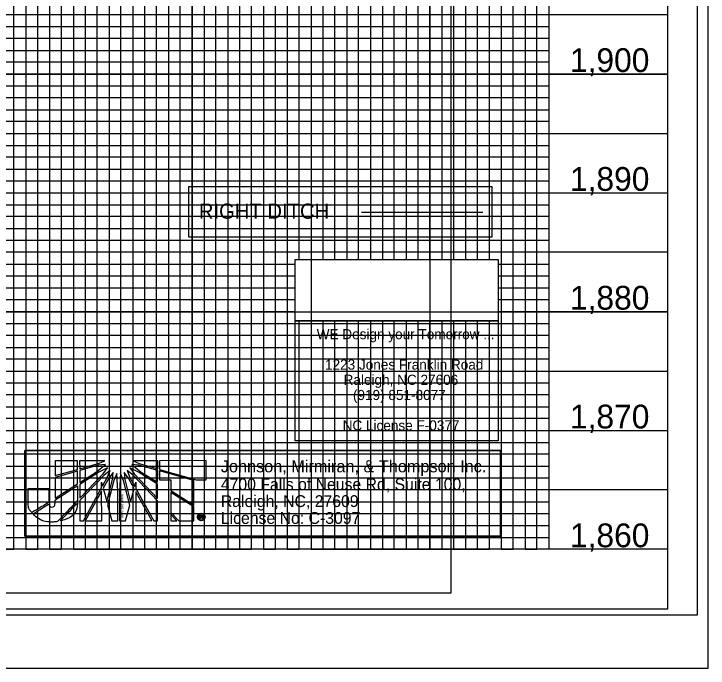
# Model space of a CAD drawing. Extents: x 557032 to 558930, y 525869 to 527437.
# Drawn here: x 558424.4 to 558716.5, y 525869.2 to 526144.6 of the extents above; entities that cross this region are included whole.
import ezdxf

# ---------------------------------------------------------------- set-up
doc = ezdxf.new("R2010")
doc.units = 0
for name, color, linetype in [('Exist Vertical Profile Vertical Axis Label', 7, 'Continuous'), ('Prop DSN Text', 7, 'Continuous'), ('Prop Grid Mask', 7, 'Continuous'), ('Prop PFL Ditch Label CELL', 7, 'Continuous'), ('Prop Vertical Profile Curve Label', 7, 'Continuous'), ('Prop VPI Label', 7, 'Continuous'), ('Raster_Level_4', 7, 'Continuous'), ('Sheet Cutting Line CELL', 7, 'Continuous'), ('Sheet DOT Grid CELL', 7, 'Continuous'), ('Sheet Layout Profile Border Port 2', 7, 'Continuous'), ('Sheet Plot Border Inside CELL', 7, 'Continuous'), ('Sheet Plot Border Outside CELL', 7, 'Continuous'), ('Sheet Profile CELL', 7, 'Continuous'), ('Sheet Profile Grid Major CELL', 7, 'Continuous'), ('Sheet Profile Grid Middle CELL', 7, 'Continuous'), ('Sheet Profile Grid Minor CELL', 7, 'Continuous')]:
    doc.layers.add(name, color=color, linetype=linetype)

msp = doc.modelspace()

# ---------------------------------------------------------------- linework, layer by layer
at = {"layer": 'Prop DSN Text'}
for p, q in [((558542.78, 525964.85), (558542.78, 526041.24)), ((558542.78, 526041.24), (558628.11, 526041.24)), ((558628.11, 526041.24), (558628.11, 525964.85)), ((558628.11, 526015.44), (558542.78, 526015.44)), ((558628.11, 525964.85), (558542.78, 525964.85))]:
    msp.add_line(p, q, dxfattribs=at)
at = {"layer": 'Prop Grid Mask'}
msp.add_lwpolyline([(558498, 526071.88), (558625.5, 526071.88), (558625.5, 526050.63), (558498, 526050.63)], close=True, dxfattribs=at)
at = {"layer": 'Prop PFL Ditch Label CELL'}
for p, q in [((558570.72, 526061.12), (558621.72, 526061.12)), ((558498, 526059.13), (558498, 526059.13))]:
    msp.add_line(p, q, dxfattribs=at)
at = {"layer": 'Prop Vertical Profile Curve Label'}
for p, q in [((558451.13, 525956.44), (558441.77, 525956.43)), ((558441.77, 525956.43), (558441.78, 525950.22)), ((558451.13, 525952.83), (558451.13, 525956.44)), ((558462.64, 525956.5), (558452.1, 525956.49)), ((558452.1, 525956.49), (558452.11, 525953.14)), ((558459.95, 525955.31), (558462.64, 525956.5)), ((558484.95, 525956.47), (558474.56, 525956.51)), ((558474.56, 525956.51), (558477.19, 525955.28)), ((558484.95, 525953.11), (558484.95, 525956.47)), ((558505.35, 525956.54), (558485.67, 525956.52)), ((558485.67, 525956.52), (558485.67, 525952.91)), ((558505.36, 525948.48), (558505.35, 525956.54)), ((558452.11, 525953.14), (558459.95, 525955.31)), ((558459.95, 525954.58), (558452.11, 525952.41)), ((558459.14, 525951.8), (558463.01, 525954.95)), ((558463.01, 525954.95), (558459.95, 525954.58)), ((558463.78, 525953.5), (558460.22, 525951.69)), ((558461.98, 525950.97), (558463.78, 525953.5)), ((558473.22, 525953.51), (558475.03, 525950.93)), ((558476.84, 525951.71), (558473.22, 525953.51)), ((558474.04, 525954.97), (558477.97, 525951.76)), ((558476.93, 525954.6), (558474.04, 525954.97)), ((558484.95, 525952.4), (558476.93, 525954.6)), ((558477.19, 525955.28), (558484.95, 525953.11)), ((558441.78, 525950.22), (558451.13, 525952.83)), ((558451.13, 525952.15), (558441.78, 525949.51)), ((558451.14, 525946.73), (558451.13, 525952.15)), ((558452.11, 525952.41), (558452.11, 525947.34)), ((558452.11, 525947.34), (558459.14, 525951.8)), ((558460.22, 525951.69), (558452.11, 525946.53)), ((558452.12, 525940.69), (558461.98, 525950.97)), ((558462.38, 525950.46), (558452.12, 525939.7)), ((558464.87, 525952.38), (558462.38, 525950.46)), ((558463.73, 525949.38), (558464.87, 525952.38)), ((558466.21, 525951.54), (558464.36, 525949.16)), ((558465.95, 525948.66), (558466.21, 525951.54)), ((558467.76, 525951.13), (558466.48, 525948.13)), ((558468.17, 525943.74), (558467.76, 525951.13)), ((558469.3, 525951.13), (558468.83, 525943.75)), ((558470.54, 525948.13), (558469.3, 525951.13)), ((558470.8, 525951.55), (558471.11, 525948.55)), ((558472.61, 525949.17), (558470.8, 525951.55)), ((558472.13, 525952.38), (558473.27, 525949.39)), ((558474.62, 525950.47), (558472.13, 525952.38)), ((558484.9, 525939.64), (558474.62, 525950.47)), ((558475.03, 525950.93), (558484.9, 525940.61)), ((558484.89, 525946.6), (558476.84, 525951.71)), ((558477.97, 525951.76), (558484.89, 525947.44)), ((558484.89, 525947.44), (558484.95, 525952.4)), ((558485.67, 525952.91), (558485.67, 525952.8)), ((558485.67, 525952.8), (558501.17, 525948.47)), ((558485.68, 525952.24), (558485.68, 525952.18)), ((558500.18, 525948.12), (558485.68, 525952.24)), ((558485.68, 525952.18), (558485.68, 525948.41)), ((558441.78, 525949.51), (558441.78, 525940.78)), ((558461.31, 525945.04), (558461.3, 525947.51)), ((558461.3, 525947.51), (558461.77, 525945.81)), ((558461.77, 525945.81), (558463.73, 525949.38)), ((558464.36, 525949.16), (558462.03, 525944.93)), ((558463.54, 525939.31), (558465.95, 525948.66)), ((558466.48, 525948.13), (558463.85, 525938.01)), ((558473.24, 525937.86), (558470.54, 525948.13)), ((558471.11, 525948.55), (558473.55, 525939.1)), ((558475.04, 525944.79), (558472.61, 525949.17)), ((558473.27, 525949.39), (558475.29, 525945.67)), ((558475.29, 525945.67), (558475.76, 525947.52)), ((558475.76, 525947.52), (558475.77, 525944.79)), ((558485.68, 525948.41), (558490.48, 525948.42)), ((558490.48, 525948.42), (558490.49, 525943.92)), ((558500.19, 525937.78), (558500.18, 525948.12)), ((558501.17, 525948.47), (558505.36, 525948.48)), ((558441.78, 525940.78), (558451.14, 525946.73)), ((558452.11, 525946.53), (558452.12, 525940.69)), ((558453.67, 525931.2), (558461.31, 525945.04)), ((558462.03, 525944.93), (558463.54, 525939.31)), ((558473.55, 525939.1), (558475.04, 525944.79)), ((558475.77, 525944.79), (558483.25, 525931.23)), ((558484.9, 525940.61), (558484.89, 525946.6)), ((558461.31, 525943.69), (558454.4, 525931.2)), ((558461.38, 525931.21), (558461.31, 525943.69)), ((558468.18, 525931.26), (558468.17, 525943.74)), ((558468.83, 525943.75), (558468.84, 525931.26)), ((558482.48, 525931.28), (558475.77, 525943.44)), ((558475.77, 525943.44), (558475.78, 525931.27)), ((558490.49, 525943.92), (558500.19, 525937.78)), ((558490.49, 525943.15), (558490.5, 525934.78)), ((558500.19, 525937.06), (558490.49, 525943.15)), ((558452.12, 525939.7), (558452.13, 525931.2)), ((558484.91, 525931.23), (558484.9, 525939.64)), ((558463.85, 525938.01), (558465.61, 525931.26)), ((558471.44, 525931.27), (558473.24, 525937.86)), ((558500.2, 525931.25), (558500.19, 525937.06)), ((558490.5, 525934.78), (558493.85, 525931.24)), ((558492.92, 525931.24), (558490.5, 525933.86)), ((558490.5, 525933.86), (558490.5, 525931.24)), ((558502.66, 525933.56), (558503.25, 525933.57)), ((558502.66, 525932.13), (558502.66, 525933.56)), ((558503.25, 525933.29), (558502.99, 525933.29)), ((558502.99, 525933.29), (558502.99, 525932.95)), ((558502.99, 525932.95), (558503.25, 525932.95)), ((558503.25, 525932.69), (558502.99, 525932.69)), ((558502.99, 525932.69), (558502.99, 525932.13)), ((558503.25, 525934.41), (558503.25, 525934.11)), ((558503.25, 525934.11), (558503.25, 525934.41)), ((558503.25, 525933.57), (558503.25, 525933.29)), ((558503.25, 525933.29), (558503.25, 525933.57)), ((558503.25, 525933.57), (558503.34, 525933.57)), ((558503.29, 525933.29), (558503.25, 525933.29)), ((558503.25, 525932.95), (558503.25, 525932.69)), ((558503.25, 525932.69), (558503.25, 525932.95)), ((558503.25, 525932.95), (558503.26, 525932.95)), ((558503.26, 525932.69), (558503.25, 525932.69)), ((558452.13, 525931.2), (558453.67, 525931.2)), ((558454.4, 525931.2), (558461.38, 525931.21)), ((558465.61, 525931.26), (558468.18, 525931.26)), ((558468.84, 525931.26), (558471.44, 525931.27)), ((558475.78, 525931.27), (558482.48, 525931.28)), ((558483.25, 525931.23), (558484.91, 525931.23)), ((558490.5, 525931.24), (558492.92, 525931.24)), ((558493.85, 525931.24), (558500.2, 525931.25)), ((558502.99, 525932.13), (558502.66, 525932.13)), ((558503.25, 525931.57), (558503.25, 525931.26)), ((558503.25, 525931.26), (558503.25, 525931.57)), ((558503.25, 525931.57), (558503.26, 525931.57)), ((558503.26, 525931.26), (558503.25, 525931.26))]:
    msp.add_line(p, q, dxfattribs=at)
for points in [[(558429.11, 525960.86), (558629.15, 525960.86), (558629.15, 525924.76), (558429.11, 525924.76)], [(558429.11, 525924.76), (558629.15, 525924.76), (558629.15, 525960.86), (558429.11, 525960.86)]]:
    msp.add_lwpolyline(points, close=True, dxfattribs=at)
for points in [[(558441.78, 525950.22), (558451.13, 525952.83), (558451.13, 525956.44), (558441.77, 525956.43), (558441.78, 525950.22)], [(558459.95, 525955.31), (558462.64, 525956.5), (558452.1, 525956.49), (558452.11, 525953.14), (558459.95, 525955.31)], [(558477.19, 525955.28), (558484.95, 525953.11), (558484.95, 525956.47), (558474.56, 525956.51), (558477.19, 525955.28)], [(558505.35, 525956.54), (558485.67, 525956.52), (558485.67, 525952.91), (558485.67, 525952.8), (558501.17, 525948.47), (558505.36, 525948.48), (558505.35, 525956.54)], [(558452.11, 525952.41), (558452.11, 525947.34), (558459.14, 525951.8), (558463.01, 525954.95), (558459.95, 525954.58), (558452.11, 525952.41)], [(558452.11, 525946.53), (558452.12, 525940.69), (558461.98, 525950.97), (558463.78, 525953.5), (558460.22, 525951.69), (558452.11, 525946.53)], [(558473.22, 525953.51), (558475.03, 525950.93), (558484.9, 525940.61), (558484.89, 525946.6), (558476.84, 525951.71), (558473.22, 525953.51)], [(558474.04, 525954.97), (558477.97, 525951.76), (558484.89, 525947.44), (558484.95, 525952.4), (558476.93, 525954.6), (558474.04, 525954.97)], [(558441.78, 525940.78), (558451.14, 525946.73), (558451.13, 525952.15), (558441.78, 525949.51), (558441.78, 525940.78)], [(558464.87, 525952.38), (558462.38, 525950.46), (558452.12, 525939.7), (558452.13, 525931.2), (558453.67, 525931.2), (558461.31, 525945.04), (558461.3, 525947.51), (558461.77, 525945.81), (558463.73, 525949.38), (558464.87, 525952.38)], [(558466.21, 525951.54), (558464.36, 525949.16), (558462.03, 525944.93), (558463.54, 525939.31), (558465.95, 525948.66), (558466.21, 525951.54)], [(558466.48, 525948.13), (558463.85, 525938.01), (558465.61, 525931.26), (558468.18, 525931.26), (558468.17, 525943.74), (558467.76, 525951.13), (558466.48, 525948.13)], [(558469.3, 525951.13), (558468.83, 525943.75), (558468.84, 525931.26), (558471.44, 525931.27), (558473.24, 525937.86), (558470.54, 525948.13), (558469.3, 525951.13)], [(558470.8, 525951.55), (558471.11, 525948.55), (558473.55, 525939.1), (558475.04, 525944.79), (558472.61, 525949.17), (558470.8, 525951.55)], [(558472.13, 525952.38), (558473.27, 525949.39), (558475.29, 525945.67), (558475.76, 525947.52), (558475.77, 525944.79), (558483.25, 525931.23), (558484.91, 525931.23), (558484.9, 525939.64), (558474.62, 525950.47), (558472.13, 525952.38)], [(558485.68, 525952.24), (558485.68, 525952.18), (558485.68, 525948.41), (558490.48, 525948.42), (558490.49, 525943.92), (558500.19, 525937.78), (558500.18, 525948.12), (558485.68, 525952.24)], [(558454.4, 525931.2), (558461.38, 525931.21), (558461.31, 525943.69), (558454.4, 525931.2)], [(558475.78, 525931.27), (558482.48, 525931.28), (558475.77, 525943.44), (558475.78, 525931.27)], [(558490.49, 525943.15), (558490.5, 525934.78), (558493.85, 525931.24), (558500.2, 525931.25), (558500.19, 525937.06), (558490.49, 525943.15), (558490.49, 525943.15)], [(558490.5, 525931.24), (558490.5, 525931.24), (558492.92, 525931.24), (558490.5, 525933.86), (558490.5, 525931.24)], [(558503.87, 525932.47), (558503.87, 525932.39), (558503.89, 525932.34), (558503.89, 525932.29), (558503.93, 525932.13), (558503.63, 525932.13)]]:
    msp.add_lwpolyline(points, dxfattribs=at)
for points, degree in [([(558439.09, 525944.8), (558439.09, 525944.8), (558430.43, 525944.79), (558430.43, 525944.79), (558430.43, 525944.79), (558430.43, 525939.37), (558430.43, 525939.37), (558430.43, 525939.37), (558430.43, 525938.8), (558430.43, 525938.8), (558430.43, 525937.1), (558430.99, 525935.75), (558431.98, 525934.63), (558431.98, 525934.63), (558439.1, 525938.96), (558439.1, 525939.07), (558439.1, 525939.07), (558439.09, 525944.8), (558439.09, 525944.8)], 3), ([(558440.44, 525937), (558439.89, 525937), (558439.41, 525937.31), (558439.21, 525938.34), (558439.21, 525938.34), (558432.49, 525934.18), (558432.49, 525934.18), (558434.56, 525932), (558437.87, 525930.71), (558440.67, 525930.71), (558441.39, 525930.71), (558441.95, 525930.77), (558442.72, 525930.93), (558442.72, 525930.93), (558451.15, 525939.65), (558451.15, 525939.65), (558451.15, 525939.65), (558451.14, 525945.95), (558451.14, 525945.95), (558451.14, 525945.95), (558441.78, 525940), (558441.78, 525940), (558441.79, 525937.63), (558441.22, 525937), (558440.44, 525937)], 3), ([(558440.44, 525937), (558439.89, 525937), (558439.41, 525937.31), (558439.21, 525938.34), (558439.21, 525938.34), (558432.49, 525934.18), (558432.49, 525934.18), (558434.56, 525932), (558437.87, 525930.71), (558440.67, 525930.71), (558441.39, 525930.71), (558441.95, 525930.77), (558442.72, 525930.93), (558442.72, 525930.93), (558451.15, 525939.65), (558451.15, 525939.65), (558451.15, 525939.65), (558451.14, 525945.95), (558451.14, 525945.95), (558451.14, 525945.95), (558441.78, 525940), (558441.78, 525940), (558441.79, 525937.63), (558441.22, 525937), (558440.44, 525937)], 3), ([(558451.15, 525938.66), (558451.15, 525938.66), (558443.86, 525931.13), (558443.86, 525931.13), (558447.43, 525932.02), (558450.98, 525934.38), (558451.15, 525938.66)], 3), ([(558503.25, 525931.26), (558502.82, 525931.26), (558502.44, 525931.42), (558502.13, 525931.73), (558501.82, 525932.03), (558501.66, 525932.41), (558501.66, 525932.85), (558501.66, 525933.29), (558501.82, 525933.67), (558502.13, 525933.95), (558502.44, 525934.25), (558502.81, 525934.41), (558503.25, 525934.41)], 3), ([(558503.25, 525934.11), (558502.9, 525934.11), (558502.6, 525933.99), (558502.35, 525933.76), (558502.1, 525933.51), (558501.97, 525933.2), (558501.97, 525932.85), (558501.97, 525932.5), (558502.11, 525932.19), (558502.35, 525931.94), (558502.6, 525931.69), (558502.9, 525931.57), (558503.25, 525931.57)], 3), ([(558503.25, 525934.41), (558503.69, 525934.41), (558504.07, 525934.26), (558504.38, 525933.96), (558504.69, 525933.67), (558504.85, 525933.29), (558504.85, 525932.85)], 3), ([(558503.26, 525931.57), (558503.62, 525931.58), (558503.91, 525931.69), (558504.16, 525931.94), (558504.41, 525932.19), (558504.54, 525932.5), (558504.54, 525932.85), (558504.54, 525933.2), (558504.41, 525933.51), (558504.16, 525933.76), (558503.91, 525934), (558503.61, 525934.11), (558503.25, 525934.11)], 3), ([(558503.26, 525932.95), (558503.47, 525932.95), (558503.57, 525933.02), (558503.57, 525933.14), (558503.57, 525933.24), (558503.48, 525933.29), (558503.29, 525933.29)], 3), ([(558504.85, 525932.85), (558504.85, 525932.41), (558504.69, 525932.03), (558504.4, 525931.72), (558504.08, 525931.42), (558503.71, 525931.26), (558503.26, 525931.26)], 3), ([(558503.51, 525932.64), (558503.47, 525932.67), (558503.39, 525932.69), (558503.26, 525932.69)], 2), ([(558503.34, 525933.57), (558503.7, 525933.57), (558503.89, 525933.42), (558503.89, 525933.14), (558503.89, 525933.01), (558503.83, 525932.9), (558503.72, 525932.82)], 3), ([(558503.63, 525932.13), (558503.59, 525932.21), (558503.56, 525932.29), (558503.56, 525932.39), (558503.56, 525932.52), (558503.55, 525932.6), (558503.51, 525932.64)], 3), ([(558503.72, 525932.82), (558503.81, 525932.77), (558503.86, 525932.66), (558503.87, 525932.47)], 2)]:
    msp.add_open_spline(points, degree=degree, dxfattribs=at)
at = {"layer": 'Prop VPI Label'}
for points in [[(558498, 526071.88), (558625.5, 526071.88), (558625.5, 526050.63), (558498, 526050.63)], [(558542.78, 526015.44), (558628.11, 526015.44), (558628.11, 525964.85), (558542.78, 525964.85)]]:
    msp.add_lwpolyline(points, close=True, dxfattribs=at)
at = {"layer": 'Raster_Level_4'}
msp.add_lwpolyline([(558253.56, 526235.09), (558608.2, 526235.09), (558608.2, 525900.76), (558253.56, 525900.76)], close=True, dxfattribs=at)
at = {"layer": 'Sheet Cutting Line CELL'}
msp.add_line((557032.45, 525869.22), (558716.45, 525869.22), dxfattribs=at)
at = {"layer": 'Sheet DOT Grid CELL'}
for p, q in [((558449.45, 526419.22), (558449.45, 525919.22)), ((558499.45, 526419.22), (558499.45, 525919.22)), ((558549.45, 526419.22), (558549.45, 525919.22)), ((558599.45, 526419.22), (558599.45, 525919.22)), ((558649.45, 526419.22), (558649.45, 525919.22)), ((557199.45, 526119.22), (558699.34, 526119.22)), ((557199.45, 526069.22), (558699.34, 526069.22)), ((557199.45, 526019.22), (558699.34, 526019.22)), ((557199.45, 525969.22), (558699.34, 525969.22))]:
    msp.add_line(p, q, dxfattribs=at)
at = {"layer": 'Sheet Layout Profile Border Port 2'}
msp.add_lwpolyline([(557249.45, 526419.22), (558649.45, 526419.22), (558649.45, 525919.22), (557249.45, 525919.22)], close=True, dxfattribs=at)
at = {"layer": 'Sheet Plot Border Inside CELL'}
msp.add_lwpolyline([(557045.45, 525891.67), (558711.95, 525891.67), (558711.95, 526946.77), (557045.45, 526946.77)], close=True, dxfattribs=at)
at = {"layer": 'Sheet Plot Border Outside CELL'}
msp.add_lwpolyline([(557032.45, 525869.22), (558716.45, 525869.22), (558716.45, 526969.22), (557032.45, 526969.22)], close=True, dxfattribs=at)
at = {"layer": 'Sheet Profile CELL'}
for p, q in [((558699.45, 525919.22), (557199.45, 525919.22)), ((557199.45, 525894.22), (558699.45, 525894.22))]:
    msp.add_line(p, q, dxfattribs=at)
msp.add_lwpolyline([(558699.45, 526944.22), (557199.45, 526944.22), (557199.45, 525894.22), (558699.45, 525894.22)], close=True, dxfattribs=at)
at = {"layer": 'Sheet Profile Grid Major CELL'}
msp.add_line((558599.45, 525919.22), (558599.45, 525919.22), dxfattribs=at)
for points in [[(558249.45, 525919.22), (558299.45, 525919.22), (558299.45, 526419.22), (558349.45, 526419.22), (558349.45, 525919.22), (558399.45, 525919.22), (558399.45, 526419.22), (558449.45, 526419.22), (558449.45, 525919.22), (558499.45, 525919.22), (558499.45, 526419.22), (558549.45, 526419.22), (558549.45, 526041.24)], [(558599.45, 526041.24), (558599.45, 526419.22), (558649.45, 526419.22), (558649.45, 525919.22)], [(558699.45, 526119.22), (557199.45, 526119.22), (557199.45, 526069.22), (558699.45, 526069.22)], [(558542.78, 526019.22), (557199.45, 526019.22), (557199.45, 526019.22), (557199.45, 525969.22), (558699.45, 525969.22)], [(558699.45, 526019.22), (558628.11, 526019.22)], [(558549.45, 526015.44), (558549.45, 525919.22), (558599.45, 525919.22), (558599.45, 525919.22), (558599.45, 526015.44)], [(558699.45, 525919.22), (557199.45, 525919.22)]]:
    msp.add_lwpolyline(points, dxfattribs=at)
at = {"layer": 'Sheet Profile Grid Middle CELL'}
for points in [[(558224.45, 526419.22), (558274.45, 526419.22), (558274.45, 525919.22), (558324.45, 525919.22), (558324.45, 526419.22), (558374.45, 526419.22), (558374.45, 525919.22), (558424.45, 525919.22), (558424.45, 526419.22), (558474.45, 526419.22), (558474.45, 525919.22), (558524.45, 525919.22), (558524.45, 526419.22), (558574.45, 526419.22), (558574.45, 526041.24)], [(558624.45, 526041.24), (558624.45, 526419.22)], [(558699.45, 526144.22), (557199.45, 526144.22), (557199.45, 526094.22), (558699.45, 526094.22)], [(558699.45, 526044.22), (557199.45, 526044.22), (557199.45, 525994.22), (558699.45, 525994.22)], [(558574.45, 526015.44), (558574.45, 525919.22), (558624.45, 525919.22), (558624.45, 526015.44)], [(558699.45, 525944.22), (557199.45, 525944.22)]]:
    msp.add_lwpolyline(points, dxfattribs=at)
at = {"layer": 'Sheet Profile Grid Minor CELL'}
for p, q in [((557249.45, 526139.22), (558649.45, 526139.22)), ((558649.45, 526134.22), (557249.45, 526134.22)), ((557249.45, 526129.22), (558649.45, 526129.22)), ((558649.45, 526124.22), (557249.45, 526124.22)), ((557249.45, 526114.22), (558649.45, 526114.22)), ((558649.45, 526109.22), (557249.45, 526109.22)), ((557249.45, 526104.22), (558649.45, 526104.22)), ((558649.45, 526099.22), (557249.45, 526099.22)), ((557249.45, 526089.22), (558649.45, 526089.22)), ((558649.45, 526084.22), (557249.45, 526084.22)), ((557249.45, 526079.22), (558649.45, 526079.22)), ((558649.45, 526074.22), (557249.45, 526074.22)), ((557249.45, 526064.22), (558649.45, 526064.22)), ((558649.45, 526059.22), (557249.45, 526059.22)), ((557249.45, 526054.22), (558649.45, 526054.22)), ((558649.45, 526049.22), (557249.45, 526049.22)), ((557249.45, 526039.22), (558542.78, 526039.22)), ((558628.11, 526039.22), (558649.45, 526039.22)), ((558542.78, 526034.22), (557249.45, 526034.22)), ((558649.45, 526034.22), (558628.11, 526034.22)), ((557249.45, 526029.22), (558542.78, 526029.22)), ((558628.11, 526029.22), (558649.45, 526029.22)), ((558542.78, 526024.22), (557249.45, 526024.22)), ((558649.45, 526024.22), (558628.11, 526024.22)), ((557249.45, 526014.22), (558649.45, 526014.22)), ((558649.45, 526009.22), (557249.45, 526009.22)), ((557249.45, 526004.22), (558649.45, 526004.22)), ((558649.45, 525999.22), (557249.45, 525999.22)), ((557249.45, 525989.22), (558649.45, 525989.22)), ((558649.45, 525984.22), (557249.45, 525984.22)), ((557249.45, 525979.22), (558649.45, 525979.22)), ((558649.45, 525974.22), (557249.45, 525974.22)), ((557249.45, 525964.22), (558649.45, 525964.22)), ((558649.45, 525959.22), (557249.45, 525959.22)), ((557249.45, 525954.22), (558649.45, 525954.22)), ((558649.45, 525949.22), (557249.45, 525949.22)), ((557249.45, 525939.22), (558649.45, 525939.22)), ((558649.45, 525934.22), (557249.45, 525934.22)), ((557249.45, 525929.22), (558649.45, 525929.22)), ((557249.45, 525924.22), (558649.45, 525924.22)), ((558649.45, 525924.22), (558649.45, 525924.22))]:
    msp.add_line(p, q, dxfattribs=at)
for points in [[(558429.45, 526419.22), (558429.45, 525919.22), (558434.45, 525919.22), (558434.45, 526419.22)], [(558439.45, 526419.22), (558439.45, 525919.22), (558444.45, 525919.22), (558444.45, 526419.22)], [(558454.45, 526419.22), (558454.45, 525919.22), (558459.45, 525919.22), (558459.45, 526419.22)], [(558464.45, 526419.22), (558464.45, 525919.22), (558469.45, 525919.22), (558469.45, 526419.22)], [(558479.45, 526419.22), (558479.45, 525919.22), (558484.45, 525919.22), (558484.45, 526419.22)], [(558489.45, 526419.22), (558489.45, 525919.22), (558494.45, 525919.22), (558494.45, 526419.22)], [(558504.45, 526419.22), (558504.45, 525919.22), (558509.45, 525919.22), (558509.45, 526419.22)], [(558514.45, 526419.22), (558514.45, 525919.22), (558519.45, 525919.22), (558519.45, 526419.22)], [(558529.45, 526419.22), (558529.45, 525919.22), (558534.45, 525919.22), (558534.45, 526419.22)], [(558539.45, 526419.22), (558539.45, 525919.22), (558544.45, 525919.22), (558544.45, 526015.44)], [(558544.45, 526041.24), (558544.45, 526419.22), (558554.45, 526419.22), (558554.45, 526041.24)], [(558559.45, 526041.24), (558559.45, 526419.22), (558564.45, 526419.22), (558564.45, 526041.24)], [(558569.45, 526041.24), (558569.45, 526419.22), (558579.45, 526419.22), (558579.45, 526041.24)], [(558584.45, 526041.24), (558584.45, 526419.22), (558589.45, 526419.22), (558589.45, 526041.24)], [(558594.45, 526041.24), (558594.45, 526419.22), (558604.45, 526419.22), (558604.45, 526041.24)], [(558609.45, 526041.24), (558609.45, 526419.22), (558614.45, 526419.22), (558614.45, 526041.24)], [(558619.45, 526041.24), (558619.45, 526419.22), (558629.45, 526419.22), (558629.45, 525919.22), (558634.45, 525919.22), (558634.45, 526419.22), (558639.45, 526419.22), (558639.45, 525919.22), (558644.45, 525919.22), (558644.45, 526419.22), (558649.45, 526419.22)], [(558554.45, 526015.44), (558554.45, 525919.22), (558559.45, 525919.22), (558559.45, 526015.44)], [(558564.45, 526015.44), (558564.45, 525919.22), (558569.45, 525919.22), (558569.45, 526015.44)], [(558579.45, 526015.44), (558579.45, 525919.22), (558584.45, 525919.22), (558584.45, 526015.44)], [(558589.45, 526015.44), (558589.45, 525919.22), (558594.45, 525919.22), (558594.45, 526015.44)], [(558604.45, 526015.44), (558604.45, 525919.22), (558609.45, 525919.22), (558609.45, 526015.44)], [(558614.45, 526015.44), (558614.45, 525919.22), (558619.45, 525919.22), (558619.45, 526015.44)]]:
    msp.add_lwpolyline(points, dxfattribs=at)

# ---------------------------------------------------------------- texts
at = {"layer": 'Exist Vertical Profile Vertical Axis Label'}
for s, p in [('1,900', (558658.31, 526120.09)), ('1,890', (558658.31, 526070.09)), ('1,880', (558658.31, 526020.09)), ('1,870', (558658.31, 525970.09)), ('1,860', (558658.31, 525920.09))]:
    msp.add_text(s, height=10, dxfattribs=at).set_placement(p)
at = {"layer": 'Prop DSN Text'}
for s, p in [('WE Design your Tomorrow ...', (558551.82, 526007.64)), ('1223 Jones Franklin Road', (558555.31, 525994.84)), ('Raleigh, NC 27606', (558563.13, 525988.44)), ('(919) 851-8077', (558567.07, 525982.04)), ('NC License F-0377', (558562.72, 525969.24))]:
    msp.add_text(s, height=4.2667, rotation=0, dxfattribs=at).set_placement(p)
at = {"layer": 'Prop PFL Ditch Label CELL'}
msp.add_text('RIGHT DITCH', height=6.3623, dxfattribs=at).set_placement((558502.25, 526058.36))
at = {"layer": 'Prop Vertical Profile Curve Label'}
for s, height, p in [('Johnson, Mirmiran, & Thompson Inc.', 5.1112, (558511.49, 525951.62)), ('4700 Falls of Neuse Rd, Suite 100, ', 4.9652, (558511.49, 525944.12)), ('Raleigh, NC, 27609', 4.9652, (558511.49, 525937.02)), ('License No: C-3097', 4.9652, (558511.49, 525929.93))]:
    msp.add_text(s, height=height, dxfattribs=at).set_placement(p)
msp.add_text('www.jmt.com', height=1.2413, rotation=270, dxfattribs=at).set_placement((558469.46, 525942.47))

doc.saveas('drawing.dxf')
